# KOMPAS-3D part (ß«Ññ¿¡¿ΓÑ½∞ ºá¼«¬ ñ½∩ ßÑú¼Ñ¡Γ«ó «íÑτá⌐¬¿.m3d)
File: created 10.03.2016 22:34:01, last saved 04.07.2016 14:55:07.
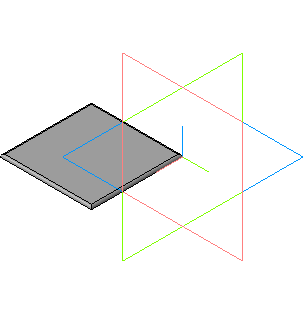
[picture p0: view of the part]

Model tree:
1. Эскиз:1
2. Операция выдавливания:1
     Расстояние 1 = 1
3. Скругление:1
     Радиус = 1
